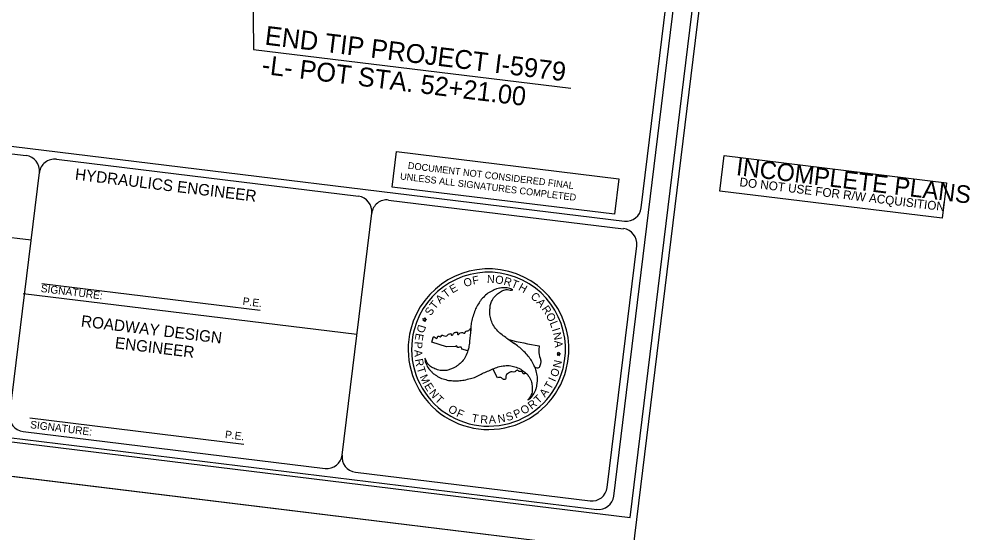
# Model space of a CAD drawing. Extents: x 1756435 to 1766932, y 416863 to 426859.
# Drawn here: x 1764409 to 1766932, y 421675 to 423037 of the extents above; entities that cross this region are included whole.
import ezdxf

# ---------------------------------------------------------------- set-up
doc = ezdxf.new("R2010")
doc.units = 0
for name, color, linetype in [('Prop Horizontal Alignment Station Label', 7, 'Continuous'), ('Sheet Cutting Line CELL', 7, 'Continuous'), ('Sheet Plan CELL', 7, 'Continuous'), ('Sheet Plot Border Inside CELL', 7, 'Continuous'), ('Sheet Plot Border Outside CELL', 7, 'Continuous'), ('Sheet Sticker Exception Certification CELL', 7, 'Continuous'), ('Sheet Sticker Incomplete CELL', 7, 'Continuous'), ('Sheet Title CELL', 7, 'Continuous')]:
    doc.layers.add(name, color=color, linetype=linetype)

# ---------------------------------------------------------------- blocks, each defined once
blk = doc.blocks.new('STICKER INCOMPLETE PLANS')
at = {"layer": 'Sheet Sticker Incomplete CELL'}
blk.add_lwpolyline([(0, -0.47), (0, 0), (2.94, 0), (2.94, -0.47)], close=True, dxfattribs=at)
for s, height, p in [('INCOMPLETE PLANS', 0.2304, (0.179, -0.236)), ('DO NOT USE FOR R/W ACQUISITION', 0.1152, (0.244, -0.375))]:
    blk.add_text(s, height=height, dxfattribs=at).set_placement(p)

msp = doc.modelspace()

# ---------------------------------------------------------------- linework, layer by layer
at = {"layer": 'Prop Horizontal Alignment Station Label'}
msp.add_lwpolyline([(1765024.5, 423553.3), (1765030.5, 422956.3), (1765872.2, 422853.3)], dxfattribs=at)
at = {"layer": 'Sheet Cutting Line CELL'}
msp.add_line((1759286.8, 422449.7), (1766036.5, 421623.8), dxfattribs=at)
at = {"layer": 'Sheet Plot Border Inside CELL'}
msp.add_lwpolyline([(1759349.9, 422533.3), (1766029.4, 421715.9), (1766546.9, 425944.9), (1759867.4, 426762.2)], close=True, dxfattribs=at)
at = {"layer": 'Sheet Plot Border Outside CELL'}
msp.add_lwpolyline([(1766576, 426032.6), (1759826.3, 426858.6), (1759286.8, 422449.7), (1766036.5, 421623.8)], close=True, dxfattribs=at)
at = {"layer": 'Sheet Sticker Exception Certification CELL'}
for p, q in [((1765398.4, 422591.6), (1765409.9, 422685.8)), ((1765409.9, 422685.8), (1765999.1, 422613.7)), ((1765999.1, 422613.7), (1765987.6, 422519.5)), ((1765987.6, 422519.5), (1765398.4, 422591.6))]:
    msp.add_line(p, q, dxfattribs=at)
at = {"layer": 'Sheet Title CELL'}
for p, q in [((1760322.1, 423197.7), (1766013.7, 422501.2)), ((1763285.7, 422814.9), (1764428, 422675.1)), ((1764508.2, 422665.1), (1765308.9, 422567.1)), ((1764384.7, 421988.6), (1764463.2, 422629.9)), ((1764441.3, 422450.7), (1763218.8, 422600.3)), ((1765389, 422557.3), (1766011.2, 422481.2)), ((1765265.6, 421880.8), (1765344, 422522.1)), ((1764469.9, 422336.2), (1765048.1, 422265.5)), ((1765717.9, 422319.3), (1765717.4, 422319)), ((1765717.9, 422319.3), (1765717.4, 422319)), ((1764420.3, 422309.8), (1765304.8, 422201.6)), ((1765482.3, 422240), (1765480, 422242.8)), ((1765480, 422242.8), (1765483.6, 422241.9)), ((1765483.6, 422241.9), (1765485.5, 422245)), ((1765485.5, 422245), (1765485.8, 422241.3)), ((1765480.4, 422236.8), (1765482.3, 422240)), ((1765483.7, 422238.2), (1765480.4, 422236.8)), ((1765486.1, 422235.3), (1765483.7, 422238.2)), ((1765485.8, 422241.3), (1765489.4, 422240.4)), ((1765489.4, 422240.4), (1765485.9, 422239)), ((1765485.9, 422239), (1765486.1, 422235.3)), ((1765503.5, 422180.1), (1765507.1, 422192.4)), ((1765542.2, 422168.5), (1765503.5, 422180.1)), ((1765566.3, 422169.3), (1765542.2, 422168.5)), ((1765707.1, 422187.1), (1765707.1, 422187.1)), ((1765599.1, 422157.8), (1765582.9, 422162.2)), ((1765838.9, 422150.9), (1765835.3, 422151.8)), ((1765835.3, 422151.8), (1765837.7, 422149)), ((1765837.7, 422149), (1765835.8, 422145.8)), ((1765835.8, 422145.8), (1765839.1, 422147.2)), ((1765840.8, 422153.9), (1765838.9, 422150.9)), ((1765839.1, 422147.2), (1765841.4, 422144.4)), ((1765841.2, 422150.3), (1765840.8, 422153.9)), ((1765844.7, 422149.5), (1765841.2, 422150.3)), ((1765841.2, 422148.1), (1765844.7, 422149.5)), ((1765841.4, 422144.4), (1765841.2, 422148.1)), ((1765677.8, 422086.3), (1765665.4, 422109.6)), ((1765665.4, 422109.6), (1765665.4, 422109.6)), ((1765859.7, 422108.3), (1765859.7, 422108.3)), ((1764437.5, 421979.9), (1765004.7, 421910.5))]:
    msp.add_line(p, q, dxfattribs=at)
for points in [[(1765985.5, 421772.4), (1766490.7, 425900.7)], [(1766058.6, 422536.3), (1766468.2, 425883.2)], [(1760008.5, 422463.1), (1765940.5, 421737.2)], [(1765967.9, 421794.9), (1766046.4, 422436.2)], [(1764419.9, 421943.6), (1765220.6, 421845.7)], [(1765300.8, 421835.8), (1765922.9, 421759.7)]]:
    msp.add_lwpolyline(points, dxfattribs=at)
for centre, radius, start, end in [((1764423.1, 422635), 40.4, 353.0234, 83.0234), ((1764503.3, 422625.2), 40.4, 83.0234, 173.0234), ((1765304, 422527), 40.4, 353.0234, 83.0234), ((1765384.1, 422517.2), 40.4, 83.0234, 173.0234), ((1766018.6, 422541.5), 40.4, 263.0234, 353.0234), ((1766006.3, 422441.3), 40.4, 353.0234, 83.0234), ((1765653.7, 422161.8), 212.9, 345.4445, 165.4445), ((1765653.7, 422161.8), 204, 345.4445, 165.4445), ((1765653.7, 422161.8), 212.9, 165.4445, 345.4445), ((1765653.7, 422161.8), 204, 165.4445, 345.4445), ((1765967.9, 423278.7), 1122.3, 251.123, 251.2226), ((1765967.9, 423278.7), 1122.3, 256.5621, 260.7681), ((1764424.8, 421983.9), 40.4, 173.0234, 263.0234), ((1765225.5, 421886), 40.4, 263.0234, 353.0234), ((1765305.7, 421876.2), 40.4, 173.0234, 263.0234), ((1765927.9, 421800), 40.4, 263.0234, 353.0234), ((1765945.4, 421777.5), 40.4, 263.0234, 353.0234)]:
    msp.add_arc(centre, radius, start, end, dxfattribs=at)
for points in [[(1765717.4, 422319), (1765713.1, 422321.4), (1765699.3, 422324.4), (1765684.2, 422323.6), (1765682.8, 422323.2), (1765674.9, 422321.4), (1765666.1, 422317.8), (1765652.2, 422310.1), (1765640.2, 422299.3), (1765635.4, 422294.7), (1765631.1, 422288.5), (1765622.7, 422275.1), (1765616.7, 422261.7), (1765611.5, 422245.5), (1765608, 422231), (1765606.6, 422215.7), (1765605.3, 422200.2), (1765603.7, 422185.2), (1765601.9, 422169.9), (1765598.1, 422155.1), (1765597.7, 422153.9), (1765591, 422138.9), (1765581.1, 422126.8), (1765569.9, 422117.4), (1765563.7, 422113.3), (1765555.4, 422109.7), (1765550.7, 422107.6), (1765540.1, 422105.3), (1765525.2, 422105.6), (1765511.6, 422110), (1765500.2, 422116.3), (1765491.2, 422126), (1765485.3, 422138.1)], [(1765758.2, 422027.5), (1765762.2, 422030), (1765771.8, 422040.5), (1765778.7, 422054), (1765779.2, 422055.3), (1765781.4, 422063.2), (1765782.7, 422072.7), (1765783.2, 422088.5), (1765779.6, 422104.2), (1765778.2, 422110.7), (1765774.9, 422117.7), (1765767.5, 422131.5), (1765758.9, 422143.4), (1765747.5, 422155.9), (1765736.6, 422166.1), (1765724.1, 422175.2), (1765711.3, 422184), (1765699.3, 422192.8), (1765686.7, 422202.2), (1765675.9, 422212.8), (1765675.1, 422213.8), (1765665.3, 422227.2), (1765659.8, 422241.9), (1765657.1, 422256.2), (1765656.9, 422263.5), (1765658, 422272.5), (1765658.4, 422277.8), (1765661.8, 422287.9), (1765669.6, 422300.9), (1765680.1, 422310.3), (1765691.2, 422317), (1765704.2, 422319.9), (1765717.4, 422319), (1765717.9, 422319.3)], [(1765507.1, 422192.4), (1765507, 422193.7), (1765509.4, 422194.5), (1765514.6, 422190.6), (1765518.2, 422192.3), (1765518.7, 422194.9), (1765521.7, 422196.8), (1765525.5, 422194.9), (1765530.3, 422198.6), (1765533.8, 422198.5), (1765540.7, 422196.7), (1765551.1, 422202.9), (1765554.7, 422202.5), (1765555, 422200), (1765557, 422199.1), (1765562.4, 422205), (1765563.5, 422205.7), (1765570.7, 422206.6), (1765572.1, 422204.9), (1765571.8, 422201.7), (1765572.5, 422200.9), (1765575, 422201.9), (1765578.9, 422204.8), (1765584.9, 422206.2), (1765590.7, 422203.9), (1765593.1, 422208.5), (1765601.4, 422211.5), (1765603.6, 422213.9), (1765604.7, 422216.8)], [(1765606.6, 422216.1), (1765606.6, 422215.7), (1765605.3, 422200.2), (1765603.7, 422185.2), (1765601.9, 422169.9), (1765599.1, 422157.8)], [(1765582.9, 422162.2), (1765582.1, 422165.6), (1765579.1, 422167.4), (1765574.3, 422166.2), (1765571.1, 422167.2), (1765568.2, 422170.7), (1765566.3, 422169.3)], [(1765777.2, 422113.3), (1765774.9, 422117.7), (1765767.5, 422131.5), (1765758.9, 422143.4), (1765747.5, 422155.9), (1765736.6, 422166.1), (1765724.1, 422175.2), (1765711.3, 422184), (1765707.1, 422187.1)], [(1765787.8, 422170.9), (1765787.2, 422156.4), (1765790.2, 422138.3), (1765792.6, 422128.3), (1765790.4, 422120.6), (1765786.3, 422112), (1765777.3, 422113.4)], [(1765485.3, 422138.1), (1765485.5, 422133.1), (1765489.8, 422119.6), (1765498, 422106.9), (1765499, 422106), (1765504.6, 422099.9), (1765512.1, 422094.2), (1765525.7, 422085.8), (1765540.9, 422081.1), (1765547.4, 422079.1), (1765555.3, 422078.5), (1765570.6, 422078), (1765585.2, 422079.4), (1765601.9, 422083), (1765616.1, 422087.2), (1765630.3, 422093.7), (1765644.3, 422100.4), (1765658.1, 422106.4), (1765672.3, 422112.4), (1765686.9, 422116.6), (1765688.5, 422116.8), (1765704.8, 422118.6), (1765720.1, 422116), (1765733.7, 422111.2), (1765740.6, 422107.8), (1765747.5, 422102.3), (1765752.1, 422099.3), (1765759.2, 422091.3), (1765766.3, 422078.2), (1765769.3, 422064.3), (1765769.5, 422051.2), (1765765.6, 422038.6), (1765758.2, 422027.5)], [(1765665.4, 422109.6), (1765672.3, 422112.4), (1765686.9, 422116.6), (1765688.5, 422116.8), (1765704.8, 422118.6), (1765720.1, 422116), (1765733.7, 422111.2), (1765740.6, 422107.8), (1765747.5, 422102.3), (1765751.7, 422099.5)], [(1765751.6, 422099.4), (1765748.8, 422096.3), (1765745.6, 422096.9), (1765741.3, 422102.6), (1765734.3, 422103), (1765731.7, 422105.6), (1765729.7, 422106.2), (1765723.3, 422101.4), (1765716.3, 422101.6), (1765703.6, 422096.5), (1765700.2, 422092.5), (1765698.5, 422082.4), (1765695.3, 422081.1), (1765692.3, 422082.5), (1765686.3, 422086.7), (1765677.8, 422086.3)]]:
    msp.add_spline(points, degree=3, dxfattribs=at)

# ---------------------------------------------------------------- block references
at = {"layer": 'Sheet Cutting Line CELL', "xscale": 201.90023598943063, "yscale": 201.90023598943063, "rotation": -6.976601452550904}
msp.add_blockref('STICKER INCOMPLETE PLANS', (1766278.3, 422675.2), dxfattribs=at)

# ---------------------------------------------------------------- texts
at = {"layer": 'Sheet Plan CELL'}
for s, p in [('END TIP PROJECT I-5979', (1765059.1, 422969.4)), ('-L- POT STA. 52+21.00', (1765050.8, 422892))]:
    msp.add_text(s, height=50, rotation=353.0234, dxfattribs=at).set_placement(p)
at = {"layer": 'Sheet Sticker Exception Certification CELL'}
for s, p in [('DOCUMENT NOT CONSIDERED FINAL', (1765439.1, 422640.2)), ('UNLESS ALL SIGNATURES COMPLETED', (1765418.5, 422612))]:
    msp.add_text(s, height=18.171, rotation=353.0234, dxfattribs=at).set_placement(p)
at = {"layer": 'Sheet Title CELL'}
for s, height, rotation, p in [(' HYDRAULICS ENGINEER', 30.285, 353.0234, (1764545.3, 422612.7)), ('O', 21.2, 17.6621, (1765591.3, 422326.1)), ('F', 21.3, 10.5152, (1765612.8, 422332.8)), ('N', 21.2, 358.4283, (1765649.4, 422337.6)), ('O', 21.3, 350.9302, (1765670.1, 422336.9)), ('R', 21.2, 344.3203, (1765692.3, 422333.3)), ('T', 21.3, 337.6706, (1765711.9, 422327.9)), ('SIGNATURE:', 20.19, 353.0234, (1764466, 422313.6)), ('T', 21.2, 36.7171, (1765541, 422296.8)), ('E', 21.2, 29.6015, (1765557.7, 422309.2)), ('H', 21.2, 330.5859, (1765731, 422319.8)), ('P.E.', 20.19, 353.0234, (1765001.2, 422279.5)), ('A', 21.3, 43.7723, (1765525.2, 422281.6)), ('C', 21.2, 318.2436, (1765763.5, 422299.3)), ('S', 21.2, 57.2008, (1765500.9, 422248.8)), ('T', 21.3, 50.8246, (1765511.8, 422265.7)), ('A', 21.2, 310.7465, (1765779.2, 422285.1)), ('R', 21.2, 304.3826, (1765793.5, 422268.6)), ('ROADWAY DESIGN', 30.283, 353.0234, (1764572.3, 422222.2)), ('O', 21.3, 297.263, (1765804.9, 422251.8)), ('D', 21.2, 253.2975, (1765468.2, 422228.6)), ('L', 21.2, 291.0293, (1765815.3, 422231.7)), ('I', 21.3, 287.04, (1765821.5, 422214.5)), ('ENGINEER', 30.28, 353.0234, (1764662.3, 422164.4)), ('E', 21.1, 259.5854, (1765461.4, 422205.2)), ('N', 21.2, 281.3399, (1765824.4, 422204.5)), ('P', 21.2, 267.1178, (1765457.7, 422182.4)), ('A', 21.2, 273.9079, (1765828.3, 422184.1)), ('A', 21.2, 273.7104, (1765456.6, 422159.8)), ('R', 21.2, 280.779, (1765458.5, 422134.7)), ('T', 21.2, 287.4296, (1765463, 422111.7)), ('N', 21.2, 77.6527, (1765844.3, 422110.5)), ('M', 21.2, 294.6646, (1765470.6, 422088.8)), ('O', 21.1, 70.4046, (1765836, 422086.3)), ('E', 21.2, 302.1314, (1765482.3, 422064.5)), ('T', 21.2, 59.6191, (1765818.3, 422053.1)), ('I', 21.3, 65.269, (1765830.4, 422073.8)), ('N', 21.3, 309.1029, (1765494.7, 422045.2)), ('T', 21.2, 315.9449, (1765510, 422026.8)), ('T', 21.2, 44.4476, (1765786.4, 422015.8)), ('A', 21.3, 52.5347, (1765803.3, 422033)), ('R', 21.3, 38.3479, (1765768.1, 422001)), ('O', 21.2, 329.2486, (1765544.5, 421997.5)), ('F', 21.2, 336.4138, (1765566.8, 421984.7)), ('T', 21.2, 349.3231, (1765607.6, 421970)), ('S', 21.1, 17.2749, (1765703.3, 421970.9)), ('P', 21.2, 24.4668, (1765725.6, 421978)), ('O', 21.3, 31.1588, (1765746.3, 421987.6)), ('SIGNATURE:', 20.19, 353.0234, (1764437.9, 421952.6)), ('R', 21.2, 356.2797, (1765631.3, 421965.8)), ('A', 21.2, 3.0328, (1765654.7, 421964.6)), ('N', 21.2, 10.0644, (1765679.7, 421966.3)), ('P.E.', 20.19, 353.0234, (1764954.4, 421926.4))]:
    msp.add_text(s, height=height, rotation=rotation, dxfattribs=at).set_placement(p)

doc.saveas('drawing.dxf')
